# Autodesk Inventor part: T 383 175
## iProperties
Company: Mayer & Mueller Schaltgeräte AG
Created: 2005-10
Part Number: T 383 175
Material: 1.0110
Description: Schalthebel
Document SubType Name: Modeling
Designer: I.Baliuc
Manufacturer: Standard
Standards Organization: Custom
Density: 7.85 g/cm^3
Author: T.Messerschmitt
Revision Number: 383175
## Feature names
1. Extrusion1
2. Extrusion2
3. Rundung1 [Fillet]
4. Extrusion3
